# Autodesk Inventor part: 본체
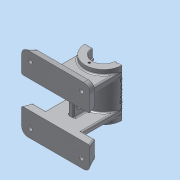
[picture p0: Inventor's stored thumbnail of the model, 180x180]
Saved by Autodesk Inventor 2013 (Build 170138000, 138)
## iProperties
Created: 2016-07
Part Number: 본체
Material: 알루미늄 6061
Document SubType Name: Modeling
Designer: Administrator
Density: 2.71 g/cm^3
Mass: 497.965 g
Surface Area: 541.299 cm^2
Volume: 183.751 cm^3
Author: Administrator
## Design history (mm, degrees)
sketch "스케치3"
  geometry: C1 r 27 at (0, 0); 1 further point
  constraints: 1 centre point, 1 coincident
  dimensions: "d4" = 54 diameter of C1
extrude "돌출1" new body sketch "스케치3" distance "d6" = 35; taper "d7" = 0 deg
sketch "스케치4"
  geometry: L1 (0, 0)-(-22, 0); L2 (-22, 0)-(-22, 21); L3 (-22, 21)-(-14, 21); L4 (-14, 21)-(-14, 23); L5 (-14, 23)-(-16, 23); L6 (-16, 23)-(-16, 35); L7 (-16, 35)-(0, 35); L8 (27, 35)-(-27, 35) reference; L9 (0, 0)-(0, 35); 1 further point
  constraints: 16 end point, 5 parallel, 2 perpendicular, 1 horizontal, 1 midpoint, 1 point on line
  dimensions: "d8" = 44 diameter of L2 L9; "d10" = 28 diameter of L4 L9; "d11" = 32 diameter of L6 L9; "d12" = 12 distance of L5.end L6.end; "d13" = 21 distance of L1.end L2.end
revolve "회전1" sketch "스케치4" stored, may be unused: angle "d14" = 90 deg
sketch "스케치5"
  geometry: C1 r 16 at (0, 0) reference; 1 further point
  constraints: 1 vertical alignment
  dimensions: "d15" = 21 distance of C1.centre point (0, 21)
hole "구멍1" sketch "스케치5" at (0, 21) diameter "d16" = 3.242; stored, may be unused: countersink angle "d20" = 90 deg, drill point angle "d22" = 118 deg; dims "d17" = 8, "d18" = 4, "d19" = 2, "d21" = 10
chamfer "모따기1" distance "d26" = 1; stored, may be unused: second distance "d27" = 2, angle "d28" = 45 deg
chamfer "모따기2" distance "d29" = 1; stored, may be unused: second distance "d30" = 2, angle "d31" = 45 deg
fillet "모깎기1" dims "d32" = 0.3
fillet "모깎기2" dims "d33" = 0.3
fillet "모깎기3" dims "d34" = 3
node "작업 평면1"
sketch "스케치7"
  geometry: L1 (-50, 55)-(50, 55); L2 (50, 55)-(50, -55); L3 (50, -55)-(-50, -55); L4 (-50, -55)-(-50, 55); 2 further points
  constraints: 8 end point, 2 parallel, 1 horizontal, 1 midpoint, 1 perpendicular, 1 vertical alignment
  dimensions: "d38" = 100 distance of L1.start L1.end; "d39" = 55 distance from line of L1 point (0, 0); "d51" = 110 distance of L1.end L2.end
extrude "돌출2" join sketch "스케치7" distance "d40" = 12; taper "d41" = -20 deg
sketch "스케치8"
  geometry: L1 (50, -55)-(-50, -55) reference; L2 (-50, -55)-(-50, 55) reference; 2 further points
  dimensions: "d42" = 12.5 distance from line of L1 point (-37.5, -42.5); "d43" = 12.5 distance from line of L2 point (-37.5, -42.5)
hole "구멍2" sketch "스케치8" at (-37.5, -42.5) diameter "d44" = 6; stored, may be unused: countersink angle "d48" = 90 deg, drill point angle "d50" = 0 deg; dims "d45" = 8, "d46" = 10, "d47" = 4, "d49" = 10
sketch "스케치9"
  geometry: L1 (50, 55)-(-50, 55) reference; L2 (50, -55)-(50, 55) reference; L3 (-50, 20)-(50, 20); L4 (50, 20)-(50, -20); L5 (50, -20)-(-50, -20); L6 (-50, -20)-(-50, 20); L7 (-50, 20)-(50, -20); L8 (50, 20)-(-50, -20); 4 further points
  constraints: 12 end point, 6 midpoint, 2 parallel, 1 horizontal, 1 perpendicular, 1 vertical alignment
  dimensions: "d52" = 35 distance from line of point (0, 55) L3
extrude "돌출3" cut sketch "스케치9" distance "d54" = 12; taper "d55" = 0 deg
sketch "스케치10"
  geometry: L1 (4.368, 12)-(95.632, 12) reference; L2 (23, 70)-(23, 12); L3 (77, 70)-(77, 12); L4 (23, 12)-(77, 12); C1 r 27 at (50, 70) reference; A1 r 27 centre (50, 70) between (23, 70) and (77, 70); 1 further point
  constraints: 6 end point, 2 perpendicular, 2 point on circle, 2 point on line, 2 tangent, 1 centre point, 1 coincident, 1 concentric, 1 parallel
extrude "돌출4" join sketch "스케치10" distance "d56" = 8; taper "d57" = 0 deg
node "작업 평면2"
sketch "스케치13"
  geometry: L1 (27, 35)-(-27, 35) reference; C1 r 5 at (0, 13); 1 further point
  constraints: 1 centre point, 1 vertical alignment
  dimensions: "d84" = 10 diameter of C1; "d86" = 22 distance from line of C1.centre L1
extrude "돌출7" join sketch "스케치13" stored distance "d87" = 8; taper "d88" = 0 deg
hole "구멍3" diameter "d91" = 5.188; stored, may be unused: countersink angle "d95" = 90 deg, drill point angle "d97" = 118 deg; dims "d92" = 6, "d93" = 4, "d94" = 2, "d96" = 8, "d148" = 10, "d149" = 10
sketch "스케치14"
  geometry: L1 (0, 0)-(-15.898, -25.441); L2 (0, 0)-(30, 0)
  constraints: 4 end point, 1 equal length, 1 horizontal
  dimensions: "d98" = 30 distance of L1.start L1.end; "d99" = 122 deg angle of L1 L2
node "작업 평면3"
sketch "스케치15"
  geometry: C1 r 6 at (0, 0); 1 further point
  constraints: 1 centre point, 1 coincident
  dimensions: "d100" = 12 diameter of C1
extrude "돌출8" join sketch "스케치15" stored distance "d102" = 10; taper "d103" = 0 deg
hole "구멍4" diameter "d106" = 5.188; stored, may be unused: countersink angle "d110" = 90 deg, drill point angle "d112" = 118 deg; dims "d107" = 6, "d108" = 4, "d109" = 2, "d111" = 8, "d144" = 10, "d145" = 10
node "작업 평면5"
sketch "스케치16"
  geometry: L1 (27, 35)-(-27, 35) reference; L2 (27, -35)-(27, 35) reference; 2 further points
  constraints: 1 other
  dimensions: "d115" = 35 distance from line of L1 point (0, 0); "d116" = 27 distance from line of point (0, 0) L2
feature "엠보싱1" sketch "스케치16" dims "d117" = 0.5, "d118" = 0
fillet "모깎기4" dims "d119" = 2
fillet "모깎기5" dims "d120" = 2
node "작업 평면6"
sketch "스케치17"
  geometry: L1 (-4, 20)-(4, 20); L2 (4, 20)-(4, -20); L3 (4, -20)-(-4, -20); L4 (-4, -20)-(-4, 20); L5 (-4, 20)-(4, -20); L6 (4, 20)-(-4, -20); L7 (50, 20)-(-50, 20) reference; 2 further points
  constraints: 12 end point, 4 midpoint, 2 parallel, 1 horizontal, 1 perpendicular
  dimensions: "d126" = 8 distance of L2.end L3.end
extrude "돌출9" join sketch "스케치17" stored distance "d128" = 10; taper "d129" = 0 deg
sketch "스케치18"
  geometry: L1 (0, 21.298)-(40, 21.298) reference; L2 (12, 13.5)-(28, 13.5); L3 (31.5, 10)-(31.5, 10); L4 (28, 6.5)-(12, 6.5); L5 (8.5, 10)-(8.5, 10); L6 (75, -22)-(40, -22) reference; A1 r 3.5 centre (12, 10) between (8.5, 10) and (12, 6.5); A2 r 3.5 centre (12, 10) between (12, 13.5) and (8.5, 10); A3 r 3.5 centre (28, 10) between (28, 6.5) and (31.5, 10); A4 r 3.5 centre (28, 10) between (31.5, 10) and (28, 13.5); 11 further points
  constraints: 8 end point, 8 point on circle, 8 tangent, 6 point on line, 5 midpoint, 4 centre point, 3 equal radius, 3 vertical alignment, 2 parallel, 1 horizontal, 1 perpendicular
  dimensions: "d130" = 23 distance of point (31.5, 6.5) point (8.5, 6.5); "d132" = 7 distance of point (31.5, 13.5) point (31.5, 6.5); "d133" = 3.5 radius of A1; "d134" = 32 distance from line of L6 A4.centre
extrude "돌출10" cut sketch "스케치18" stored distance "d135" = 10; taper "d136" = 0 deg
fillet "모깎기8" dims "d137" = 2
fillet "모깎기9" dims "d138" = 2
fillet "모깎기10" dims "d139" = 2
fillet "모깎기11" dims "d140" = 10
fillet "모깎기12" dims "d141" = 10
fillet "모깎기13" dims "d142" = 2
fillet "모깎기14" dims "d143" = 2
node "솔리드1"
pattern_circular "원형 패턴1" dims angle "d24" = 360 deg
mirror "대칭1"
mirror "대칭2"
mirror "대칭3"
mirror "대칭4"
other parameters: "d114" = 27, "d125" = -48
